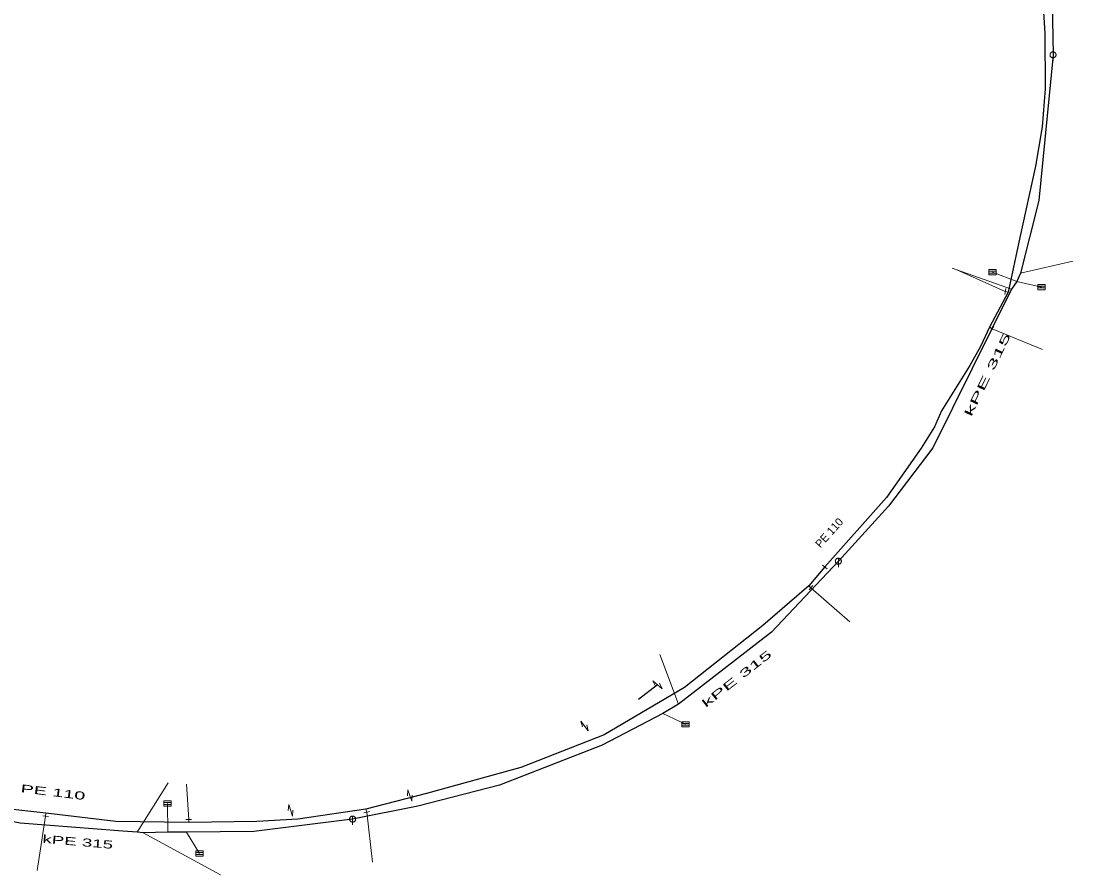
# Model space of a CAD drawing. Extents: x -687468 to -685917, y -974192 to -973456.
# Drawn here: x -686255.8 to -686168.2, y -973710.6 to -973639.5 of the extents above; entities that cross this region are included whole.
import ezdxf
from ezdxf.enums import TextEntityAlignment as Align

# ---------------------------------------------------------------- set-up
doc = ezdxf.new("R2010")
doc.units = 0
doc.header["$LTSCALE"] = 0.27
for name, color, linetype, lineweight in [('1', 7, 'Continuous', 13), ('11', 7, 'Continuous', 13), ('13', 7, 'Continuous', 13), ('14', 7, 'Continuous', 25), ('17', 7, 'Continuous', 25), ('22', 7, 'Continuous', 13), ('31', 7, 'Continuous', 13), ('34', 7, 'Continuous', 13)]:
    doc.layers.add(name, color=color, linetype=linetype, lineweight=lineweight)

msp = doc.modelspace()

# ---------------------------------------------------------------- linework, layer by layer
at = {"layer": '11'}
for p, q in [((-686168.219, -973659.53), (-686172.6, -973660.52)), ((-686174.92, -973660.44), (-686172.89, -973661.219)), ((-686170.84, -973661.68), (-686172.89, -973661.219)), ((-686202.64, -973692.27), (-686201.063, -973696.397)), ((-686200.5, -973698.07), (-686202.392, -973697.182)), ((-686243.59, -973702.949), (-686246.158, -973707.061)), ((-686243.64, -973704.66), (-686243.596, -973707.061)), ((-686239.23, -973710.609), (-686245.66, -973707.1)), ((-686240.969, -973708.82), (-686242.066, -973707.061))]:
    msp.add_line(p, q, dxfattribs=at)
msp.add_lwpolyline([(-686178.28, -973660.12), (-686177.899, -973660.25), (-686173.329, -973661.859)], dxfattribs=at)
at = {"layer": '13'}
for p, q in [((-686173.854, -973662.057), (-686177.899, -973660.25)), ((-686174.938, -973665.146), (-686170.75, -973666.879)), ((-686190.039, -973686.702), (-686186.8, -973689.539)), ((-686241.873, -973705.999), (-686242.05, -973703.059)), ((-686253.789, -973705.717), (-686254.48, -973710.239)), ((-686227.046, -973705.381), (-686226.57, -973709.55))]:
    msp.add_line(p, q, dxfattribs=at)
at = {"layer": '14', "lineweight": 13}
for p, q in [((-686173.854, -973662.057), (-686173.609, -973662.11)), ((-686174.938, -973665.146), (-686175.16, -973665.03)), ((-686190.039, -973686.702), (-686190.23, -973686.539)), ((-686227.046, -973705.381), (-686227.109, -973705.14)), ((-686253.789, -973705.717), (-686253.76, -973705.469)), ((-686241.873, -973705.999), (-686241.87, -973706.25))]:
    msp.add_line(p, q, dxfattribs=at)
at = {"layer": '14'}
msp.add_line((-686202.826, -973694.783), (-686204.399, -973696.02), dxfattribs=at)
for points in [[(-686180.69, -973608.329), (-686177.42, -973613.78), (-686177.129, -973614.719), (-686173.8, -973620.3), (-686172.17, -973624.579), (-686172.07, -973625.16), (-686170.02, -973635.02), (-686169.879, -973642.359)], [(-686169.879, -973642.359), (-686171.07, -973654.489), (-686172.6, -973660.52), (-686172.89, -973661.219), (-686173.329, -973661.859), (-686179.879, -973675.05), (-686183.579, -973679.93), (-686187.76, -973684.5)], [(-686187.76, -973684.5), (-686193.32, -973690.399), (-686200.109, -973695.66), (-686201.063, -973696.397), (-686202.392, -973697.182), (-686207.42, -973699.809), (-686215.98, -973703.129), (-686222.789, -973704.879), (-686228.219, -973705.96)], [(-686228.219, -973705.96), (-686236.46, -973706.98), (-686242.066, -973707.061), (-686243.596, -973707.061), (-686245.66, -973707.1), (-686246.158, -973707.061), (-686247.352, -973706.969), (-686255.91, -973706.289), (-686263.43, -973704.82)]]:
    msp.add_lwpolyline(points, dxfattribs=at)
at = {"layer": '17'}
for points in [[(-686170.809, -973636.51), (-686170.55, -973640.579), (-686170.53, -973645.19), (-686170.789, -973648.34), (-686171.35, -973651.629), (-686172.64, -973657.55), (-686173.609, -973662.11), (-686175.16, -973665.03), (-686175.91, -973666.62), (-686176.82, -973668.219), (-686179.17, -973671.98), (-686179.739, -973673.309), (-686180.87, -973675.1), (-686183.76, -973679.21), (-686188.889, -973684.979)], [(-686188.889, -973684.979), (-686190.23, -973686.539), (-686194.059, -973689.859), (-686200.579, -973695.02), (-686207.27, -973698.96), (-686214.21, -973701.68), (-686222.059, -973703.829), (-686227.109, -973705.14), (-686232.77, -973705.96), (-686236.199, -973706.17), (-686241.87, -973706.25), (-686247.949, -973706.17), (-686253.76, -973705.469), (-686258.78, -973704.92), (-686262.609, -973704.19), (-686268.649, -973703.309), (-686273.87, -973701.469)]]:
    msp.add_lwpolyline(points, dxfattribs=at)
at = {"layer": '22'}
for p, q in [((-686169.878, -973642.107), (-686169.879, -973642.851)), ((-686175.215, -973660.369), (-686174.617, -973660.369)), ((-686175.215, -973660.514), (-686174.617, -973660.514)), ((-686171.135, -973661.609), (-686170.537, -973661.609)), ((-686171.135, -973661.755), (-686170.537, -973661.755)), ((-686187.759, -973684.248), (-686187.76, -973684.992)), ((-686200.795, -973697.999), (-686200.197, -973697.999)), ((-686200.795, -973698.144), (-686200.197, -973698.144)), ((-686243.935, -973704.589), (-686243.337, -973704.589)), ((-686243.935, -973704.735), (-686243.337, -973704.735)), ((-686228.218, -973705.708), (-686228.219, -973706.451)), ((-686241.264, -973708.749), (-686240.666, -973708.749)), ((-686241.264, -973708.894), (-686240.666, -973708.894))]:
    msp.add_line(p, q, dxfattribs=at)
for points in [[(-686169.627, -973642.359), (-686169.628, -973642.333), (-686169.632, -973642.307), (-686169.638, -973642.281), (-686169.648, -973642.257), (-686169.66, -973642.233), (-686169.674, -973642.211), (-686169.691, -973642.19), (-686169.709, -973642.172), (-686169.73, -973642.155), (-686169.752, -973642.141), (-686169.776, -973642.129), (-686169.8, -973642.119), (-686169.826, -973642.113), (-686169.852, -973642.109), (-686169.878, -973642.107), (-686169.904, -973642.108), (-686169.93, -973642.112), (-686169.956, -973642.118), (-686169.981, -973642.128), (-686170.004, -973642.14), (-686170.026, -973642.154), (-686170.047, -973642.171), (-686170.065, -973642.189), (-686170.082, -973642.21), (-686170.096, -973642.232), (-686170.108, -973642.256), (-686170.118, -973642.28), (-686170.125, -973642.306), (-686170.129, -973642.332), (-686170.13, -973642.358), (-686170.13, -973642.384), (-686170.126, -973642.41), (-686170.119, -973642.436), (-686170.109, -973642.461), (-686170.097, -973642.484), (-686170.083, -973642.506), (-686170.066, -973642.527), (-686170.048, -973642.545), (-686170.027, -973642.562), (-686170.005, -973642.576), (-686169.982, -973642.588), (-686169.957, -973642.598), (-686169.931, -973642.605), (-686169.905, -973642.609), (-686169.879, -973642.611), (-686169.853, -973642.61), (-686169.827, -973642.606), (-686169.801, -973642.599), (-686169.777, -973642.589), (-686169.753, -973642.577), (-686169.731, -973642.563), (-686169.71, -973642.546), (-686169.692, -973642.528), (-686169.675, -973642.507), (-686169.661, -973642.485), (-686169.649, -973642.462), (-686169.639, -973642.437), (-686169.633, -973642.411), (-686169.629, -973642.385)], [(-686175.215, -973660.223), (-686174.617, -973660.223), (-686174.617, -973660.659), (-686175.215, -973660.659)], [(-686171.135, -973661.463), (-686170.537, -973661.463), (-686170.537, -973661.9), (-686171.135, -973661.9)], [(-686187.508, -973684.5), (-686187.509, -973684.474), (-686187.513, -973684.448), (-686187.519, -973684.422), (-686187.529, -973684.398), (-686187.541, -973684.374), (-686187.555, -973684.352), (-686187.572, -973684.331), (-686187.59, -973684.313), (-686187.611, -973684.296), (-686187.633, -973684.282), (-686187.657, -973684.27), (-686187.681, -973684.26), (-686187.707, -973684.254), (-686187.733, -973684.25), (-686187.759, -973684.248), (-686187.785, -973684.249), (-686187.811, -973684.253), (-686187.837, -973684.259), (-686187.862, -973684.269), (-686187.885, -973684.281), (-686187.907, -973684.295), (-686187.928, -973684.312), (-686187.946, -973684.33), (-686187.963, -973684.351), (-686187.977, -973684.373), (-686187.989, -973684.397), (-686187.999, -973684.421), (-686188.006, -973684.447), (-686188.01, -973684.473), (-686188.012, -973684.499), (-686188.011, -973684.525), (-686188.007, -973684.551), (-686188, -973684.577), (-686187.99, -973684.602), (-686187.978, -973684.625), (-686187.964, -973684.647), (-686187.947, -973684.668), (-686187.929, -973684.686), (-686187.908, -973684.703), (-686187.886, -973684.717), (-686187.863, -973684.729), (-686187.838, -973684.739), (-686187.812, -973684.746), (-686187.786, -973684.75), (-686187.76, -973684.752), (-686187.734, -973684.751), (-686187.708, -973684.747), (-686187.682, -973684.74), (-686187.658, -973684.73), (-686187.634, -973684.718), (-686187.612, -973684.704), (-686187.591, -973684.687), (-686187.573, -973684.669), (-686187.556, -973684.648), (-686187.542, -973684.626), (-686187.53, -973684.603), (-686187.52, -973684.578), (-686187.514, -973684.552), (-686187.51, -973684.526)], [(-686200.795, -973697.853), (-686200.197, -973697.853), (-686200.197, -973698.289), (-686200.795, -973698.289)], [(-686243.935, -973704.443), (-686243.337, -973704.443), (-686243.337, -973704.88), (-686243.935, -973704.88)], [(-686227.967, -973705.96), (-686227.968, -973705.934), (-686227.972, -973705.908), (-686227.978, -973705.882), (-686227.988, -973705.858), (-686228, -973705.834), (-686228.014, -973705.812), (-686228.031, -973705.791), (-686228.049, -973705.773), (-686228.07, -973705.756), (-686228.092, -973705.742), (-686228.116, -973705.73), (-686228.14, -973705.72), (-686228.166, -973705.714), (-686228.192, -973705.71), (-686228.218, -973705.708), (-686228.244, -973705.709), (-686228.27, -973705.713), (-686228.296, -973705.719), (-686228.321, -973705.729), (-686228.344, -973705.741), (-686228.366, -973705.755), (-686228.387, -973705.772), (-686228.405, -973705.79), (-686228.422, -973705.811), (-686228.436, -973705.833), (-686228.448, -973705.857), (-686228.458, -973705.881), (-686228.465, -973705.907), (-686228.469, -973705.933), (-686228.471, -973705.959), (-686228.47, -973705.985), (-686228.466, -973706.011), (-686228.459, -973706.037), (-686228.449, -973706.062), (-686228.437, -973706.085), (-686228.423, -973706.107), (-686228.406, -973706.128), (-686228.388, -973706.146), (-686228.367, -973706.163), (-686228.345, -973706.177), (-686228.322, -973706.189), (-686228.297, -973706.199), (-686228.271, -973706.206), (-686228.245, -973706.21), (-686228.219, -973706.212), (-686228.193, -973706.211), (-686228.167, -973706.207), (-686228.141, -973706.2), (-686228.117, -973706.19), (-686228.093, -973706.178), (-686228.071, -973706.164), (-686228.05, -973706.147), (-686228.032, -973706.129), (-686228.015, -973706.108), (-686228.001, -973706.086), (-686227.989, -973706.063), (-686227.979, -973706.038), (-686227.973, -973706.012), (-686227.969, -973705.986)], [(-686241.264, -973708.603), (-686240.666, -973708.603), (-686240.666, -973709.039), (-686241.264, -973709.039)]]:
    msp.add_lwpolyline(points, close=True, dxfattribs=at)
at = {"layer": '31'}
for p, q in [((-686203.212, -973694.45), (-686202.983, -973694.907)), ((-686209.201, -973697.797), (-686209.075, -973698.291)), ((-686223.619, -973703.512), (-686223.659, -973704.021)), ((-686233.543, -973704.746), (-686233.584, -973705.255))]:
    msp.add_line(p, q, dxfattribs=at)
for points in [[(-686203.212, -973694.45), (-686202.439, -973695.115), (-686202.668, -973694.658)], [(-686209.201, -973697.797), (-686208.588, -973698.61), (-686208.714, -973698.116)], [(-686223.619, -973703.512), (-686223.3, -973704.481), (-686223.26, -973703.972)], [(-686233.543, -973704.746), (-686233.226, -973705.715), (-686233.185, -973705.206)]]:
    msp.add_lwpolyline(points, dxfattribs=at)
at = {"layer": '34'}
for p, q in [((-686173.905, -973662.299), (-686173.802, -973661.814)), ((-686175.054, -973665.365), (-686174.821, -973664.926)), ((-686188.703, -973685.143), (-686189.074, -973684.814)), ((-686190.2, -973686.89), (-686189.877, -973686.513)), ((-686227.286, -973705.443), (-686226.805, -973705.318)), ((-686253.542, -973705.746), (-686254.035, -973705.687)), ((-686242.12, -973706.002), (-686241.625, -973705.995))]:
    msp.add_line(p, q, dxfattribs=at)

# ---------------------------------------------------------------- texts
at = {"layer": '1'}
for s, rotation, width, p in [('kPE 315 ', 64, 2.25, (-686174.911, -973668.863)), ('kPE 315 ', 38, 2.1, (-686195.816, -973694.381)), ('PE 110', 353, 1.85, (-686253.213, -973704.05)), ('kPE 315 ', 355, 1.75, (-686250.921, -973708.201))]:
    msp.add_text(s, height=0.6667, rotation=rotation, dxfattribs=dict(at, width=width)).set_placement(p, align=Align.CENTER)
msp.add_text('PE 110', height=0.6667, rotation=48, dxfattribs=at).set_placement((-686188.275, -973682.355), align=Align.CENTER)

doc.saveas('drawing.dxf')
